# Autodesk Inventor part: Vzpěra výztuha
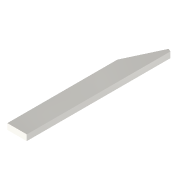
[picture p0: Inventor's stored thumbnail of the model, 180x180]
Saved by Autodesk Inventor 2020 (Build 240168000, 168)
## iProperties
Created: 2025-03
Part Number: Vzpěra výztuha
Material: Ocel
Document SubType Name: Modeling
Designer: doma
Density: 7.85 g/cm^3
Appearance: Ocel
Mass: 129.662 g
Surface Area: 74.6489 cm^2
Volume: 16.5175 cm^3
Author: doma
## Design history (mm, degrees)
sketch "Náčrt1"
  geometry: L1 (-10, -3)-(10, -3); L2 (10, -3)-(10, 3); L3 (10, 3)-(-10, 3); L4 (-10, 3)-(-10, -3); L5 (-10, -3)-(10, 3); L6 (10, -3)-(-10, 3); 1 further point
  constraints: 12 end point, 2 midpoint, 2 parallel, 1 horizontal, 1 perpendicular
  dimensions: "d0" = 20 distance of L3.end L2.end; "d1" = 6 distance of L2.end L1.end
extrude "Vysunutí1" new body sketch "Náčrt1" distance "d2" = 150; taper "d3" = 0 deg
chamfer "Zkosení2" distance "d7" = 15; stored, may be unused: second distance "d8" = 2, angle "d9" = 65 deg
sketch "Náčrt2"
  geometry: L1 (20, 150)-(15, 150) reference; L2 (15, 150)-(29.049, 143.449); L3 (15, 150)-(30.502, 150); L4 (29.049, 143.449)-(22.777, 157.288); L5 (22.777, 157.288)-(15, 150); 1 further point
  constraints: 8 end point, 1 equal length, 1 horizontal
  dimensions: "d10" = 25 deg angle of L2 L3
extrude "Vysunutí2" cut sketch "Náčrt2" distance "d11" = 140; taper "d12" = 0 deg
chamfer "Zkosení3" distance "d13" = 2; stored, may be unused: second distance "d14" = 2, angle "d15" = 45 deg
node "Těleso1"
